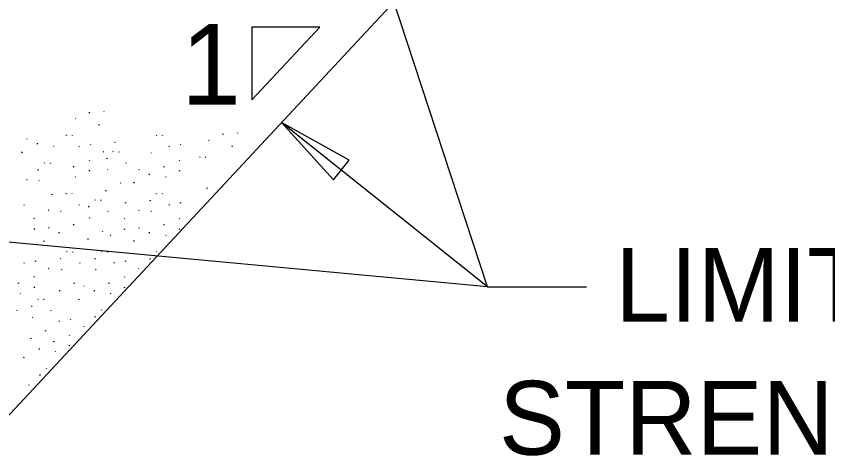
# Model space of a CAD drawing. Extents: x -1609 to 1184, y -412 to 394.
# Drawn here: x -934.514 to -931.437, y -270.051 to -268.384 of the extents above; entities that cross this region are included whole.
import ezdxf

# ---------------------------------------------------------------- set-up
doc = ezdxf.new("R2010")
doc.units = 0
for name, color, linetype in [('Default', 7, 'Continuous'), ('SH_Data', 7, 'Continuous'), ('ST_Text', 7, 'Continuous')]:
    doc.layers.add(name, color=color, linetype=linetype)

msp = doc.modelspace()

# ---------------------------------------------------------------- linework, layer by layer
at = {"layer": 'Default'}
for p, q in [((-931.5914, -266.7286), (-934.5714, -269.9286)), ((-933.6205, -268.4254), (-933.6205, -268.7016)), ((-933.3634, -268.4254), (-933.6205, -268.4254)), ((-933.3634, -268.4254), (-933.6205, -268.7016))]:
    msp.add_line(p, q, dxfattribs=at)
msp.add_lwpolyline([(-933.3118, -269.0047), (-933.2517, -268.9294), (-933.508, -268.7868)], close=True, dxfattribs=at)
at = {"layer": 'ST_Text'}
for p, q in [((-932.7272, -269.4098), (-933.6079, -266.7286)), ((-934.2372, -268.751), (-934.2356, -268.7475)), ((-934.1827, -268.7434), (-934.1811, -268.7458)), ((-934.2911, -268.7713), (-934.2895, -268.7736)), ((-934.2014, -268.7965), (-934.1999, -268.793)), ((-932.7272, -269.4098), (-933.508, -268.7868)), ((-934.3258, -268.834), (-934.3242, -268.8364)), ((-934.3035, -268.8349), (-934.3019, -268.8373)), ((-933.9838, -268.834), (-933.9822, -268.8364)), ((-933.9614, -268.8349), (-933.9599, -268.8373)), ((-933.7311, -268.8326), (-933.7295, -268.8291)), ((-933.6767, -268.825), (-933.6751, -268.8274)), ((-934.4739, -268.8483), (-934.4723, -268.8507)), ((-934.435, -268.8658), (-934.4347, -268.8693)), ((-934.2332, -268.8721), (-934.2317, -268.8686)), ((-934.1403, -268.8631), (-934.1387, -268.8596)), ((-933.8912, -268.8721), (-933.8896, -268.8686)), ((-933.785, -268.8529), (-933.7835, -268.8552)), ((-934.4926, -268.9014), (-934.491, -268.8979)), ((-934.3735, -268.8762), (-934.372, -268.8785)), ((-934.2771, -268.8767), (-934.2756, -268.8791)), ((-934.1842, -268.8972), (-934.1826, -268.8996)), ((-934.148, -268.8959), (-934.1464, -268.8982)), ((-934.1256, -268.8968), (-934.1241, -268.8991)), ((-934.0045, -268.9015), (-934.0029, -268.9038)), ((-933.9351, -268.8767), (-933.9335, -268.8791)), ((-933.6954, -268.8781), (-933.6938, -268.8746)), ((-934.2384, -268.9293), (-934.2369, -268.9317)), ((-934.1711, -268.9249), (-934.1696, -268.9214)), ((-933.8964, -268.9293), (-933.8948, -268.9317)), ((-933.8198, -268.9156), (-933.8182, -268.9179)), ((-933.7974, -268.9165), (-933.7959, -268.9188)), ((-934.4314, -268.968), (-934.4299, -268.9644)), ((-934.4083, -268.9389), (-934.4067, -268.9412)), ((-934.3859, -268.9398), (-934.3844, -268.9421)), ((-934.2968, -268.9557), (-934.2952, -268.9521)), ((-934.1687, -268.9633), (-934.1671, -268.9657)), ((-934.0993, -268.9385), (-934.0977, -268.9409)), ((-934.0494, -268.9642), (-934.0478, -268.9665)), ((-933.9548, -268.9557), (-933.9532, -268.9521)), ((-934.2911, -268.992), (-934.2895, -268.9944)), ((-934.2372, -268.9718), (-934.2356, -268.9682)), ((-934.0105, -268.9816), (-934.0102, -268.9851)), ((-933.949, -268.992), (-933.9475, -268.9944)), ((-933.8951, -268.9718), (-933.8936, -268.9682)), ((-934.4754, -269.0021), (-934.4738, -269.0045)), ((-934.429, -269.0063), (-934.4274, -269.0087)), ((-934.119, -269.0175), (-934.1174, -269.014)), ((-934.0681, -269.0173), (-934.0665, -269.0137)), ((-934.3793, -269.0606), (-934.3777, -269.057)), ((-934.3258, -269.0547), (-934.3242, -269.0571)), ((-934.3035, -269.0556), (-934.3019, -269.058)), ((-934.1748, -269.0435), (-934.1744, -269.047)), ((-933.9838, -269.0547), (-933.9822, -269.0571)), ((-933.9614, -269.0556), (-933.9599, -269.058)), ((-933.7907, -269.0372), (-933.7892, -269.0337)), ((-934.2167, -269.0792), (-934.2151, -269.0815)), ((-934.1943, -269.0801), (-934.1928, -269.0824)), ((-934.0069, -269.0838), (-934.0053, -269.0803)), ((-934.4858, -269.0974), (-934.4843, -269.0998)), ((-934.3929, -269.118), (-934.3913, -269.1203)), ((-934.2771, -269.0974), (-934.2756, -269.0998)), ((-934.2398, -269.1082), (-934.2382, -269.1047)), ((-934.0999, -269.0929), (-934.0983, -269.0893)), ((-934.0509, -269.118), (-934.0493, -269.1203)), ((-933.9351, -269.0974), (-933.9335, -269.0998)), ((-933.8912, -269.0929), (-933.8896, -269.0893)), ((-934.4471, -269.1501), (-934.4456, -269.1524)), ((-934.3465, -269.1222), (-934.345, -269.1246)), ((-934.2374, -269.1466), (-934.2358, -269.149)), ((-934.168, -269.1218), (-934.1664, -269.1242)), ((-934.1051, -269.1501), (-934.1035, -269.1524)), ((-934.0045, -269.1222), (-934.0029, -269.1246)), ((-933.8964, -269.1501), (-933.8948, -269.1524)), ((-932.7272, -269.4098), (-935.3714, -269.1641)), ((-934.2968, -269.1764), (-934.2952, -269.1729)), ((-933.9548, -269.1764), (-933.9532, -269.1729)), ((-934.4458, -269.1925), (-934.4443, -269.189)), ((-934.3914, -269.1849), (-934.3898, -269.1873)), ((-934.3526, -269.2024), (-934.3522, -269.2059)), ((-934.1877, -269.2008), (-934.1861, -269.1973)), ((-934.1038, -269.1925), (-934.1022, -269.189)), ((-934.0494, -269.1849), (-934.0478, -269.1873)), ((-934.0105, -269.2024), (-934.0102, -269.2059)), ((-933.8951, -269.1925), (-933.8936, -269.189)), ((-934.4101, -269.238), (-934.4086, -269.2345)), ((-934.2434, -269.2268), (-934.2431, -269.2303)), ((-934.1577, -269.2128), (-934.1562, -269.2151)), ((-934.0681, -269.238), (-934.0665, -269.2345)), ((-933.949, -269.2128), (-933.9475, -269.2151)), ((-934.3467, -269.3043), (-934.3451, -269.3007)), ((-934.3235, -269.2752), (-934.322, -269.2775)), ((-934.3012, -269.2761), (-934.2996, -269.2784)), ((-934.2156, -269.3046), (-934.214, -269.301)), ((-934.1925, -269.2755), (-934.1909, -269.2778)), ((-934.1701, -269.2764), (-934.1686, -269.2787)), ((-934.0069, -269.3046), (-934.0053, -269.301)), ((-933.9838, -269.2755), (-933.9822, -269.2778)), ((-934.4858, -269.3182), (-934.4843, -269.3205)), ((-934.4419, -269.3136), (-934.4404, -269.3101)), ((-934.2749, -269.3179), (-934.2733, -269.3202)), ((-934.1438, -269.3182), (-934.1422, -269.3205)), ((-934.0999, -269.3136), (-934.0983, -269.3101)), ((-934.3929, -269.3387), (-934.3913, -269.3411)), ((-934.3443, -269.3426), (-934.3427, -269.345)), ((-934.2132, -269.3429), (-934.2116, -269.3453)), ((-934.0509, -269.3387), (-934.0493, -269.3411)), ((-934.5055, -269.3972), (-934.5039, -269.3936)), ((-934.4471, -269.3708), (-934.4456, -269.3732)), ((-934.2945, -269.3968), (-934.2929, -269.3933)), ((-934.1634, -269.3972), (-934.1619, -269.3936)), ((-934.1051, -269.3708), (-934.1035, -269.3732)), ((-934.4458, -269.4132), (-934.4443, -269.4097)), ((-934.3503, -269.4228), (-934.3499, -269.4263)), ((-934.2581, -269.4056), (-934.2565, -269.408)), ((-934.2192, -269.4231), (-934.2188, -269.4266)), ((-934.1038, -269.4132), (-934.1022, -269.4097)), ((-932.7272, -269.4098), (-932.3524, -269.4098)), ((-934.4998, -269.4335), (-934.4982, -269.4358)), ((-934.4329, -269.4559), (-934.4314, -269.4583)), ((-934.4106, -269.4568), (-934.409, -269.4592)), ((-934.2768, -269.4587), (-934.2752, -269.4552)), ((-934.1577, -269.4335), (-934.1562, -269.4358)), ((-934.4561, -269.485), (-934.4545, -269.4815)), ((-934.5122, -269.4971), (-934.5106, -269.4995)), ((-934.3843, -269.4986), (-934.3827, -269.501)), ((-934.1925, -269.4962), (-934.1909, -269.4986)), ((-934.1701, -269.4971), (-934.1699, -269.4975)), ((-934.4537, -269.5234), (-934.4521, -269.5257)), ((-934.3525, -269.5389), (-934.3509, -269.5413)), ((-934.3086, -269.5343), (-934.307, -269.5308)), ((-934.2156, -269.5253), (-934.214, -269.5218)), ((-934.4039, -269.5776), (-934.4023, -269.5741)), ((-934.2596, -269.5594), (-934.258, -269.5618)), ((-934.4597, -269.6035), (-934.4593, -269.6071)), ((-934.3138, -269.5915), (-934.3122, -269.5939)), ((-934.3721, -269.6179), (-934.3706, -269.6144)), ((-934.3125, -269.634), (-934.3109, -269.6304)), ((-934.4279, -269.6438), (-934.4275, -269.6474)), ((-934.3664, -269.6542), (-934.3649, -269.6566)), ((-934.4855, -269.6795), (-934.4839, -269.676)), ((-934.4012, -269.717), (-934.3996, -269.7193)), ((-934.3788, -269.7179), (-934.3773, -269.7202)), ((-934.4243, -269.746), (-934.4227, -269.7425)), ((-934.4682, -269.7802), (-934.4667, -269.7825))]:
    msp.add_line(p, q, dxfattribs=at)

# ---------------------------------------------------------------- texts
at = {"layer": 'SH_Data'}
for s, height, p in [('1', 0.3054, (-933.8891, -268.7187)), ('LIMITS - LOW', 0.28, (-932.2434, -269.5426)), ('STRENGTH MORTAR', 0.28, (-932.6837, -270.0466))]:
    msp.add_text(s, height=height, dxfattribs=at).set_placement(p)

doc.saveas('drawing.dxf')
